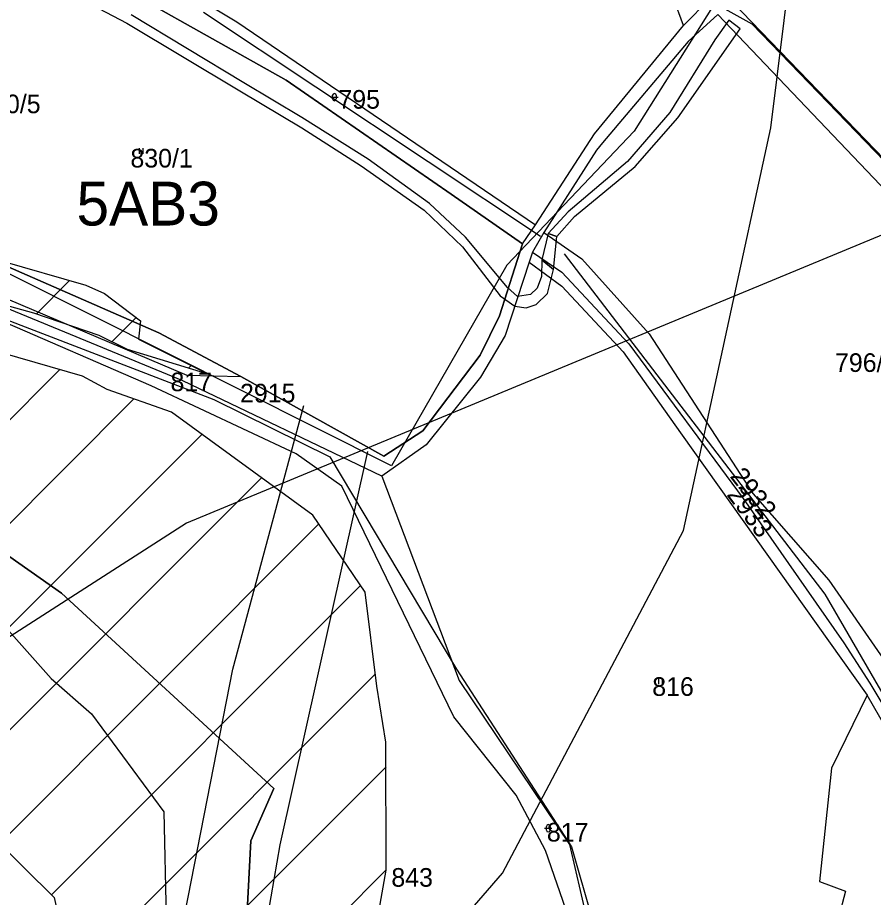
# Model space of a CAD drawing. Extents: x -564810 to -550519, y -1045831 to -1034011.
# Drawn here: x -554954.1 to -554719.8, y -1037954.1 to -1037713.3 of the extents above; entities that cross this region are included whole.
import ezdxf

# ---------------------------------------------------------------- set-up
doc = ezdxf.new("R2010")
doc.units = 0
for name, color, linetype in [('Biokoridory', 7, 'Continuous'), ('Interakční prvky', 7, 'Continuous'), ('KN stav', 7, 'Continuous'), ('Lesní porost', 7, 'Continuous'), ('Obvod KPU', 7, 'Continuous'), ('Parcelní čísla', 7, 'Continuous'), ('Polní cesty stavající', 7, 'Continuous'), ('STG', 7, 'Continuous'), ('Vrstva 16', 7, 'Continuous'), ('Vrstva 4', 7, 'Continuous'), ('Vrstva 5', 7, 'Continuous'), ('zamokř ploch', 7, 'Continuous')]:
    doc.layers.add(name, color=color, linetype=linetype)

msp = doc.modelspace()

# ---------------------------------------------------------------- linework, layer by layer
at = {"layer": 'Biokoridory'}
for points in [[(-554796.72, -1038757.4), (-554746.33, -1038713.88), (-554739.46, -1038652.04), (-554764.65, -1038550.12), (-554807.02, -1038437.89), (-554841.38, -1038338.25), (-554866.57, -1038268.39), (-554902.08, -1038207.7), (-554928.42, -1038061.11), (-554895.2, -1037891.62), (-554875.74, -1037819.47)], [(-554858.31, -1037832.03), (-554882.36, -1037939.68), (-554899.54, -1038039.32), (-554913.28, -1038102.3), (-554881.21, -1038204.23), (-554823.95, -1038296.99), (-554787.31, -1038421.82), (-554748.37, -1038538.63), (-554716.3, -1038643.99), (-554719.74, -1038719.58), (-554786.16, -1038781.42)]]:
    msp.add_lwpolyline(points, dxfattribs=at)
at = {"layer": 'Interakční prvky'}
for p, q in [((-554753.04, -1037715.05), (-554912.64, -1037625.95)), ((-554903.25, -1037711.83), (-554810.96, -1037773.11)), ((-554654.3, -1037817.46), (-554753.04, -1037715.05)), ((-555022.14, -1037771.01), (-554900.43, -1037817.78)), ((-554804.51, -1037777.95), (-554733.17, -1037871.09)), ((-554900.43, -1037817.78), (-554868.59, -1037833.51)), ((-554868.59, -1037833.51), (-554833.93, -1037891.57)), ((-554733.17, -1037871.09), (-554709.8, -1037911.32)), ((-554833.93, -1037891.57), (-554802.49, -1037940.19)), ((-554802.49, -1037940.19), (-554776.7, -1038030.5))]:
    msp.add_line(p, q, dxfattribs=at)
at = {"layer": 'KN stav'}
for p, q in [((-554954.18, -1037678.4), (-554894.07, -1037714.44)), ((-554937.27, -1037698.55), (-554880.61, -1037730.41)), ((-554880.61, -1037730.41), (-554937.27, -1037698.55)), ((-554771.84, -1037715.4), (-554775.08, -1037706.44)), ((-554764.57, -1037708.05), (-554771.84, -1037715.4)), ((-554758.37, -1037709.05), (-554662.15, -1037808.73)), ((-554894.07, -1037714.44), (-554812.34, -1037770.01)), ((-554762.4, -1037712.38), (-554770.58, -1037719.79)), ((-554685.22, -1037793.46), (-554762.4, -1037712.38)), ((-554796.19, -1037745.07), (-554771.84, -1037715.4)), ((-554770.58, -1037719.79), (-554793.95, -1037747.53)), ((-554880.61, -1037730.41), (-554835.43, -1037761.57)), ((-554835.43, -1037761.57), (-554880.61, -1037730.41)), ((-554812.34, -1037770.01), (-554796.19, -1037745.07)), ((-554793.95, -1037747.53), (-554795.62, -1037749.51)), ((-554795.62, -1037749.51), (-554810.03, -1037772.07)), ((-554835.43, -1037761.57), (-554815.87, -1037775.19)), ((-554815.87, -1037775.19), (-554835.43, -1037761.57)), ((-554815.87, -1037775.19), (-554812.34, -1037770.01)), ((-554810.03, -1037772.07), (-554813.14, -1037777.5)), ((-554810.03, -1037772.07), (-554799.68, -1037779.31)), ((-554815.87, -1037775.19), (-554822.22, -1037794.87)), ((-554822.22, -1037794.87), (-554815.87, -1037775.19)), ((-554813.14, -1037777.5), (-554814.07, -1037780.2)), ((-554813.14, -1037777.5), (-554805.15, -1037782.9)), ((-554799.68, -1037779.31), (-554781.21, -1037799.81)), ((-554915.4, -1037799.51), (-554961.11, -1037779.53)), ((-554961.11, -1037779.53), (-554915.4, -1037799.51)), ((-554814.07, -1037780.2), (-554820.66, -1037800.25)), ((-554814.07, -1037780.2), (-554805.1, -1037786.77)), ((-554805.15, -1037782.9), (-554786.81, -1037802.51)), ((-554805.1, -1037786.77), (-554788.31, -1037804.77)), ((-554917.53, -1037814.01), (-554973, -1037790.06)), ((-554956.98, -1037790.27), (-554907.82, -1037811.15)), ((-554908.91, -1037812.72), (-554958.97, -1037792.09)), ((-554822.22, -1037794.87), (-554827.52, -1037805.65)), ((-554827.52, -1037805.65), (-554822.22, -1037794.87)), ((-554892.96, -1037811.51), (-554915.4, -1037799.51)), ((-554915.4, -1037799.51), (-554892.96, -1037811.51)), ((-554820.66, -1037800.25), (-554827.4, -1037811.67)), ((-554781.21, -1037799.81), (-554752.84, -1037843.55)), ((-554786.81, -1037802.51), (-554755.46, -1037844.89)), ((-554827.52, -1037805.65), (-554843.17, -1037826.35)), ((-554843.17, -1037826.35), (-554827.52, -1037805.65)), ((-554788.31, -1037804.77), (-554772.64, -1037826.87)), ((-554854.42, -1037838.75), (-554908.91, -1037812.72)), ((-554907.82, -1037811.15), (-554892.96, -1037811.51)), ((-554853.88, -1037833.3), (-554892.96, -1037811.51)), ((-554892.96, -1037811.51), (-554853.88, -1037833.3)), ((-554827.4, -1037811.67), (-554842.27, -1037830.19)), ((-554877.86, -1037832.62), (-554917.53, -1037814.01)), ((-554843.17, -1037826.35), (-554853.88, -1037833.3)), ((-554853.88, -1037833.3), (-554843.17, -1037826.35)), ((-554772.64, -1037826.87), (-554721.57, -1037898.73)), ((-554842.27, -1037830.19), (-554854.42, -1037838.75)), ((-554865.39, -1037841.52), (-554877.86, -1037832.62)), ((-554854.42, -1037838.75), (-554833.25, -1037894.67)), ((-554834.68, -1037904.66), (-554865.39, -1037841.52)), ((-554752.84, -1037843.55), (-554731.99, -1037867.19)), ((-554755.46, -1037844.89), (-554727.97, -1037884.36)), ((-554942.1, -1037870.83), (-554969.27, -1037851.66)), ((-554731.99, -1037867.19), (-554717.08, -1037888.82)), ((-554942.1, -1037870.83), (-554883.99, -1037924.26)), ((-554727.97, -1037884.36), (-554720.77, -1037895.39)), ((-554833.25, -1037894.67), (-554803.06, -1037939.53)), ((-554720.77, -1037895.39), (-554710.02, -1037913.66)), ((-554721.57, -1037898.73), (-554731.34, -1037918.64)), ((-554702.39, -1037931.98), (-554721.57, -1037898.73)), ((-554817.66, -1037926.11), (-554834.68, -1037904.66)), ((-554731.34, -1037918.64), (-554734.55, -1037949.69)), ((-554890.25, -1037938.53), (-554883.99, -1037924.26)), ((-554809.64, -1037941.25), (-554817.66, -1037926.11)), ((-554891.36, -1037959.64), (-554890.25, -1037938.53)), ((-554803.06, -1037939.53), (-554789.53, -1037997.9)), ((-554800.42, -1037967.57), (-554809.64, -1037941.25)), ((-554734.55, -1037949.69), (-554727.5, -1037952.35)), ((-554727.5, -1037952.35), (-554731.54, -1037967.69))]:
    msp.add_line(p, q, dxfattribs=at)
at = {"layer": 'Lesní porost'}
for p, q in [((-554949.04, -1037794.39), (-554939.86, -1037785.21)), ((-554928.34, -1037801.97), (-554921.69, -1037795.32)), ((-555015.98, -1037883.07), (-554942.53, -1037809.62)), ((-554907.33, -1037809.25), (-554906.6, -1037808.52)), ((-555001.75, -1037897.13), (-554922.28, -1037817.65)), ((-554987.53, -1037911.19), (-554903.68, -1037827.34)), ((-554973.3, -1037925.24), (-554887.31, -1037839.25)), ((-554959.08, -1037939.3), (-554871.64, -1037851.86)), ((-554944.85, -1037953.36), (-554860.21, -1037868.72)), ((-554939.25, -1037976.05), (-554856.19, -1037892.98)), ((-554934.14, -1037999.22), (-554853.25, -1037918.33)), ((-554873.55, -1037966.91), (-554853.18, -1037946.54))]:
    msp.add_line(p, q, dxfattribs=at)
for points in [[(-555025.75, -1037768.71), (-555018.71, -1037754.38), (-554987.4, -1037761.22), (-554985.47, -1037768.41), (-554975.01, -1037766.12), (-554958.98, -1037779.73), (-554935.46, -1037786.47), (-554930.28, -1037788.78), (-554920.47, -1037796.25), (-554920.98, -1037801.3), (-554901.7, -1037810.97), (-554924.05, -1037804.12), (-554931.74, -1037800.27), (-554949.67, -1037794.18), (-554967.18, -1037789.29), (-554975.59, -1037789.14), (-554991.45, -1037779.58), (-555004.11, -1037771.95)], [(-554924.31, -1038043.79), (-554913.37, -1038037.96), (-554882.46, -1038026.72), (-554898.59, -1037999.32), (-554879.33, -1037961.71), (-554863.57, -1037975.89), (-554856.33, -1037964.24), (-554853.18, -1037946.6), (-554853.27, -1037911.61), (-554855.78, -1037896.26), (-554858.98, -1037870.53), (-554873.26, -1037849.47), (-554912, -1037821.28), (-554929.58, -1037815.08), (-554936.31, -1037811.42), (-554958.12, -1037805.1), (-554976.94, -1037790.09), (-554992.49, -1037782.34), (-555026.65, -1037771.6), (-555039.2, -1037769.13), (-555054.86, -1037776.63), (-555067.38, -1037788.47), (-555084.68, -1037815.18), (-554944.09, -1037954.11)]]:
    msp.add_lwpolyline(points, close=True, dxfattribs=at)
at = {"layer": 'Obvod KPU'}
for p, q in [((-554969.27, -1037851.66), (-554942.1, -1037870.83)), ((-554942.1, -1037870.83), (-554883.99, -1037924.28)), ((-554883.99, -1037924.28), (-554890.25, -1037938.55)), ((-554890.25, -1037938.55), (-554891.36, -1037959.66))]:
    msp.add_line(p, q, dxfattribs=at)
at = {"layer": 'Polní cesty stavající'}
for p, q in [((-554961.3, -1037695.19), (-554924.25, -1037714.78)), ((-554892.22, -1037731.15), (-554923.05, -1037712.51)), ((-554759.4, -1037713.95), (-554763.26, -1037719.39)), ((-554756.28, -1037716.37), (-554759.4, -1037713.95)), ((-554924.25, -1037714.78), (-554893.26, -1037733.3)), ((-554763.26, -1037719.39), (-554775.58, -1037739.21)), ((-554876.27, -1037740.65), (-554892.22, -1037731.15)), ((-554893.26, -1037733.3), (-554876.27, -1037743.43)), ((-554858.18, -1037752.01), (-554876.27, -1037740.65)), ((-554775.58, -1037739.21), (-554787.13, -1037752.66)), ((-554785.03, -1037753.99), (-554773.36, -1037740.73)), ((-554876.27, -1037743.43), (-554860.05, -1037753.86)), ((-554787.13, -1037752.66), (-554803.39, -1037766.45)), ((-554801.66, -1037767.69), (-554785.03, -1037753.99)), ((-554820.02, -1037787.14), (-554831.5, -1037773.32)), ((-554808.82, -1037772.33), (-554806.49, -1037773.16)), ((-554806.49, -1037773.16), (-554808.82, -1037772.33)), ((-554810.58, -1037779.53), (-554810.66, -1037784.17)), ((-554807.38, -1037782.19), (-554810.58, -1037779.53)), ((-554810.58, -1037779.53), (-554807.38, -1037782.19)), ((-554810.66, -1037784.17), (-554811.85, -1037787.3)), ((-554809.05, -1037788.75), (-554807.38, -1037782.19)), ((-554817.29, -1037789.62), (-554820.02, -1037787.14)), ((-554813.7, -1037789.07), (-554817.29, -1037789.62)), ((-554811.85, -1037787.3), (-554813.7, -1037789.07)), ((-554812.16, -1037791.83), (-554809.05, -1037788.75)), ((-554817.98, -1037792.29), (-554814.93, -1037792.7)), ((-554814.93, -1037792.7), (-554812.16, -1037791.83))]:
    msp.add_line(p, q, dxfattribs=at)
for points in [[(-554773.36, -1037740.73), (-554756.28, -1037716.37)], [(-554831.5, -1037773.32), (-554841.33, -1037764.17), (-554858.18, -1037752.01)], [(-554860.05, -1037753.86), (-554842.77, -1037766.01), (-554832.31, -1037776.02)], [(-554803.39, -1037766.45), (-554808.82, -1037772.33)], [(-554806.49, -1037773.16), (-554801.66, -1037767.69)], [(-554808.82, -1037772.33), (-554810.58, -1037779.53)], [(-554807.38, -1037782.19), (-554806.49, -1037773.16)], [(-554832.31, -1037776.02), (-554822.01, -1037789.39), (-554817.98, -1037792.29)]]:
    msp.add_lwpolyline(points, dxfattribs=at)
at = {"layer": 'STG'}
msp.add_lwpolyline([(-554880.2, -1038015.38), (-554821.41, -1037947.39), (-554771.81, -1037853.67), (-554747.93, -1037743.42), (-554740.58, -1037684.62), (-554740.58, -1037629.49), (-554758.95, -1037587.22), (-554790.18, -1037559.66), (-554819.58, -1037522.91), (-554825.09, -1037508.21), (-554856.32, -1037447.57), (-554871.02, -1037423.68), (-554915.11, -1037423.68), (-554959.2, -1037445.73)], dxfattribs=at)
at = {"layer": 'Vrstva 16'}
msp.add_lwpolyline([(-553156.59, -1036068.23), (-553271.19, -1036329.95), (-553326.01, -1036402.23), (-553438.12, -1036581.7), (-553500.41, -1036678.91), (-553537.78, -1036773.63), (-553654.88, -1036898.25), (-553794.4, -1036983), (-553946.38, -1037072.73), (-554030.85, -1037138.79), (-554140.47, -1037236), (-554172.86, -1037275.88), (-554409.55, -1037435.4), (-554469.35, -1037482.76), (-554516.68, -1037530.12), (-554559.04, -1037579.97), (-554569, -1037664.72), (-554661.19, -1037749.47), (-554907.84, -1037851.66), (-555066.31, -1037953.36)], dxfattribs=at)
at = {"layer": 'Vrstva 4'}
for p, q in [((-554962.05, -1037875.03), (-554944.92, -1037894.15)), ((-554944.92, -1037894.15), (-554933.84, -1037903.85)), ((-554933.84, -1037903.85), (-554914.12, -1037930.64)), ((-554914.12, -1037930.64), (-554913.17, -1037969.14))]:
    msp.add_line(p, q, dxfattribs=at)
at = {"layer": 'Vrstva 5'}
msp.add_lwpolyline([(-554905.54, -1037545.67), (-554741.2, -1037637.28), (-554692.53, -1037675.08), (-554761.24, -1037706), (-554785.29, -1037744.36), (-554820.22, -1037781.01), (-554851.72, -1037835.98), (-554974.83, -1037774.14)], dxfattribs=at)
at = {"layer": 'zamokř ploch'}
for p, q in [((-554868.36, -1037735.04), (-554866.36, -1037735.04)), ((-554867.86, -1037735.54), (-554867.86, -1037734.54)), ((-554866.86, -1037734.54), (-554866.86, -1037735.54)), ((-554920.85, -1037749.05), (-554920.85, -1037750.55)), ((-554919.85, -1037749.05), (-554919.85, -1037750.55)), ((-554778.69, -1037894.17), (-554778.69, -1037895.67)), ((-554777.69, -1037894.17), (-554777.69, -1037895.67)), ((-554809.84, -1037935.14), (-554807.84, -1037935.14)), ((-554809.34, -1037935.64), (-554809.34, -1037934.64)), ((-554808.34, -1037934.64), (-554808.34, -1037935.64))]:
    msp.add_line(p, q, dxfattribs=at)
for centre, start, end in [((-554867.36, -1037734.54), 0, 180), ((-554867.36, -1037735.54), 180, 0), ((-554808.84, -1037934.64), 0, 180), ((-554808.84, -1037935.64), 180, 0)]:
    msp.add_arc(centre, 0.5, start, end, dxfattribs=at)

# ---------------------------------------------------------------- texts
at = {"layer": 'Parcelní čísla'}
for s, p in [('795', (-554866.29, -1037738.2)), ('830/5', (-554964.88, -1037739.44)), ('830/1', (-554923.22, -1037754.3)), ('796/1', (-554730.34, -1037810.24)), ('817', (-554912.25, -1037815.52)), ('2915', (-554893.22, -1037818.59)), ('816', (-554780.37, -1037898.9)), ('817', (-554809.21, -1037938.76)), ('843', (-554851.79, -1037951.13))]:
    msp.add_text(s, height=5.1, dxfattribs=at).set_placement(p)
for s, rotation, p in [('2932', 307.4828, (-554759.27, -1037838.85)), ('2933', 306.5046, (-554760.15, -1037843.86))]:
    msp.add_text(s, height=5.1, rotation=rotation, dxfattribs=at).set_placement(p)
at = {"layer": 'STG'}
msp.add_text('5AB3', height=12, dxfattribs=at).set_placement((-554937.98, -1037770.18))

doc.saveas('drawing.dxf')
